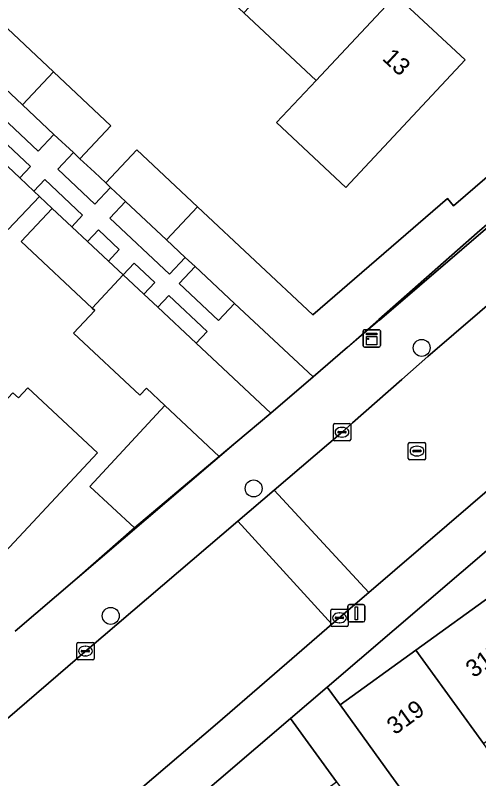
# Model space of a CAD drawing. Extents: x 159039 to 160102, y 381214 to 382524.
# Drawn here: x 159360.87 to 159387.61, y 381551.65 to 381595.72 of the extents above; entities that cross this region are included whole.
import ezdxf

# ---------------------------------------------------------------- set-up
doc = ezdxf.new("R2010")
doc.units = 0
for name, color, linetype in [('IMGEO_Boom', 7, 'Continuous'), ('IMGEO_Erf', 7, 'Continuous'), ('IMGEO_Groenvoorziening', 7, 'Continuous'), ('IMGEO_Kast', 7, 'Continuous'), ('IMGEO_Kolk', 7, 'Continuous'), ('IMGEO_Lichtmast', 7, 'Continuous'), ('IMGEO_Muur', 7, 'Continuous'), ('IMGEO_Pand', 7, 'Continuous'), ('IMGEO_Pand_nummerreeks', 7, 'Continuous'), ('IMGEO_Rijbaan_lokaal_gesloten', 7, 'Continuous'), ('IMGEO_Rijbaan_lokaal_open', 7, 'Continuous'), ('IMGEO_Rioolput', 7, 'Continuous'), ('IMGEO_Voetpad_open', 7, 'Continuous')]:
    doc.layers.add(name, color=color, linetype=linetype)

msp = doc.modelspace()

# ---------------------------------------------------------------- linework, layer by layer
at = {"layer": 'IMGEO_Boom'}
for centre in [(159384.322, 381576.519), (159374.624, 381568.41), (159366.375, 381561.05)]:
    msp.add_circle(centre, 0.489, dxfattribs=at)
at = {"layer": 'IMGEO_Erf'}
for points in [[(159358.121, 381620.029), (159362.065, 381616.336), (159366.187, 381612.475), (159370.397, 381608.534), (159374.52, 381604.672), (159378.667, 381600.788), (159382.839, 381596.881), (159386.831, 381593.143), (159379.941, 381585.785), (159375.948, 381589.524), (159378.229, 381591.959), (159374.057, 381595.866), (159369.91, 381599.75), (159365.786, 381603.611), (159361.577, 381607.553), (159357.455, 381611.414)], [(159359.739, 381595.573), (159363.073, 381592.45), (159366.39, 381589.344), (159364.602, 381587.436), (159365.432, 381586.658), (159366.093, 381586.039), (159367.881, 381587.947), (159371.392, 381584.659), (159378.048, 381578.425), (159385.803, 381585.139), (159386.165, 381584.722), (159388.093, 381586.391)], [(159360.868, 381560.164), (159364.448, 381563.227), (159367.747, 381566.141), (159365.174, 381568.516), (159369.495, 381573.198), (159368.434, 381574.191), (159368.052, 381573.783), (159364.224, 381577.368), (159365.451, 381578.677), (159365.305, 381578.814), (159361.204, 381582.655), (159362.999, 381584.572), (159362.261, 381585.263), (159360.466, 381583.346), (159357.233, 381586.374), (159353.085, 381590.258), (159354.881, 381592.176)], [(159389.45, 381584.825), (159387.521, 381583.155), (159381.857, 381578.152), (159381.88, 381578.125), (159388.939, 381584.182)], [(159403.941, 381578.38), (159378.876, 381556.936), (159379.618, 381555.911), (159383.989, 381559.075), (159388.621, 381562.428)], [(159360.734, 381573.932), (159361.052, 381573.634), (159361.598, 381574.217), (159365.612, 381570.457), (159358.919, 381563.31)], [(159383.781, 381540.929), (159381.468, 381544.123), (159383.599, 381545.666), (159382.675, 381546.943), (159380.544, 381545.4), (159377.268, 381549.925), (159379.399, 381551.468), (159376.754, 381555.121), (159362.339, 381542.788)]]:
    msp.add_lwpolyline(points, dxfattribs=at)
at = {"layer": 'IMGEO_Groenvoorziening'}
for points in [[(159358.954, 381592.724), (159358.057, 381591.767), (159362.196, 381587.88), (159363.098, 381588.843), (159361.285, 381590.541)], [(159357.412, 381591.058), (159356.787, 381590.39), (159359.028, 381588.291), (159361.125, 381586.327), (159361.752, 381586.998)], [(159365.432, 381586.658), (159364.602, 381587.436), (159364.22, 381587.793), (159363.316, 381586.828), (159365.459, 381584.816), (159366.366, 381585.783), (159366.093, 381586.039)], [(159362.566, 381586.235), (159361.939, 381585.565), (159362.261, 381585.263), (159362.999, 381584.572), (159364.128, 381583.515), (159364.756, 381584.186)], [(159367.233, 381584.971), (159366.325, 381584.002), (159369.768, 381580.769), (159370.68, 381581.743), (159369.604, 381582.751)], [(159365.663, 381583.337), (159365.035, 381582.666), (159366.245, 381581.534), (159366.873, 381582.205)], [(159367.73, 381581.404), (159367.101, 381580.732), (159368.293, 381579.616), (159368.922, 381580.288)], [(159371.246, 381581.214), (159370.333, 381580.239), (159372.604, 381578.106), (159373.52, 381579.084)], [(159369.724, 381579.537), (159369.095, 381578.864), (159371.31, 381576.79), (159371.941, 381577.463)]]:
    msp.add_lwpolyline(points, close=True, dxfattribs=at)
at = {"layer": 'IMGEO_Kast'}
for p, q in [((159380.938, 381576.646), (159380.938, 381577.487)), ((159380.938, 381577.487), (159380.938, 381576.646)), ((159381.013, 381577.571), (159381.854, 381577.571)), ((159381.854, 381577.571), (159381.013, 381577.571)), ((159381.938, 381577.496), (159381.938, 381576.655)), ((159381.938, 381576.655), (159381.938, 381577.496)), ((159381.863, 381576.571), (159381.022, 381576.571)), ((159381.022, 381576.571), (159381.863, 381576.571))]:
    msp.add_line(p, q, dxfattribs=at)
for points in [[(159381.133, 381577.361), (159381.733, 381577.361), (159381.733, 381577.276), (159381.133, 381577.276), (159381.133, 381577.361)], [(159381.133, 381577.186), (159381.733, 381577.186), (159381.733, 381576.697), (159381.133, 381576.697), (159381.133, 381577.186)]]:
    msp.add_lwpolyline(points, dxfattribs=at)
msp.add_circle((159381.217, 381577.035), 0.0377, dxfattribs=at)
for centre, start, end in [((159381.016, 381577.493), 92.4484, 184.2845), ((159381.016, 381577.493), 92.4484, 184.2845), ((159381.86, 381577.493), 2.4484, 94.2845), ((159381.86, 381577.493), 2.4484, 94.2845), ((159381.016, 381576.649), 182.4484, 274.2845), ((159381.016, 381576.649), 182.4484, 274.2845), ((159381.86, 381576.649), 272.4484, 4.2845), ((159381.86, 381576.649), 272.4484, 4.2845)]:
    msp.add_arc(centre, 0.0779, start, end, dxfattribs=at)
at = {"layer": 'IMGEO_Kolk'}
for p, q in [((159379.224, 381571.228), (159379.224, 381572.08)), ((159379.299, 381572.154), (159380.151, 381572.154)), ((159379.712, 381571.934), (159379.737, 381571.934)), ((159380.225, 381572.08), (159380.225, 381571.228)), ((159379.483, 381571.648), (159379.483, 381571.66)), ((159379.921, 381571.611), (159379.523, 381571.611)), ((159379.526, 381571.697), (159379.924, 381571.697)), ((159379.967, 381571.66), (159379.967, 381571.648)), ((159380.151, 381571.154), (159379.299, 381571.154)), ((159379.735, 381571.374), (159379.71, 381571.374)), ((159379.075, 381560.512), (159379.075, 381561.364)), ((159379.15, 381561.438), (159380.002, 381561.438)), ((159380.076, 381561.364), (159380.076, 381560.512)), ((159379.334, 381560.932), (159379.334, 381560.944)), ((159379.772, 381560.895), (159379.374, 381560.895)), ((159379.377, 381560.981), (159379.775, 381560.981)), ((159379.563, 381561.218), (159379.588, 381561.218)), ((159379.818, 381560.944), (159379.818, 381560.932)), ((159380.002, 381560.438), (159379.15, 381560.438)), ((159379.586, 381560.658), (159379.561, 381560.658)), ((159364.414, 381558.591), (159364.414, 381559.443)), ((159364.489, 381559.517), (159365.341, 381559.517)), ((159364.902, 381559.297), (159364.927, 381559.297)), ((159365.415, 381559.443), (159365.415, 381558.591)), ((159364.673, 381559.011), (159364.673, 381559.023)), ((159365.111, 381558.974), (159364.713, 381558.974)), ((159364.716, 381559.06), (159365.114, 381559.06)), ((159364.925, 381558.737), (159364.9, 381558.737)), ((159365.157, 381559.023), (159365.157, 381559.011)), ((159365.341, 381558.517), (159364.489, 381558.517))]:
    msp.add_line(p, q, dxfattribs=at)
for points in [[(159379.224, 381571.228), (159379.224, 381572.08)], [(159379.299, 381572.154), (159380.151, 381572.154)], [(159380.225, 381572.08), (159380.225, 381571.228)], [(159380.151, 381571.154), (159379.299, 381571.154)], [(159379.075, 381560.512), (159379.075, 381561.364)], [(159379.15, 381561.438), (159380.002, 381561.438)], [(159380.076, 381561.364), (159380.076, 381560.512)], [(159380.002, 381560.438), (159379.15, 381560.438)], [(159364.414, 381558.591), (159364.414, 381559.443)], [(159364.489, 381559.517), (159365.341, 381559.517)], [(159365.415, 381559.443), (159365.415, 381558.591)], [(159365.341, 381558.517), (159364.489, 381558.517)]]:
    msp.add_lwpolyline(points, dxfattribs=at)
for centre, radius, start, end in [((159379.301, 381572.078), 0.0765, 91.552, 178.448), ((159379.301, 381572.078), 0.0765, 91.552, 178.448), ((159380.149, 381572.078), 0.0765, 1.552, 88.448), ((159380.149, 381572.078), 0.0765, 1.552, 88.448), ((159379.523, 381571.657), 0.0403, 85.8775, 175.7526), ((159379.52, 381571.647), 0.0366, 178.938, 274.7102), ((159379.924, 381571.654), 0.043, 264.8664, 352.4533), ((159379.928, 381571.659), 0.0386, 1.7309, 96.639), ((159379.301, 381571.23), 0.0765, 181.552, 268.448), ((159379.301, 381571.23), 0.0765, 181.552, 268.448), ((159380.149, 381571.23), 0.0765, 271.552, 358.448), ((159380.149, 381571.23), 0.0765, 271.552, 358.448), ((159379.152, 381561.362), 0.0765, 91.552, 178.448), ((159379.152, 381561.362), 0.0765, 91.552, 178.448), ((159380, 381561.362), 0.0765, 1.552, 88.448), ((159380, 381561.362), 0.0765, 1.552, 88.448), ((159379.374, 381560.941), 0.0403, 85.8775, 175.7526), ((159379.371, 381560.931), 0.0366, 178.938, 274.7102), ((159379.775, 381560.938), 0.043, 264.8664, 352.4533), ((159379.779, 381560.943), 0.0386, 1.7309, 96.639), ((159379.152, 381560.514), 0.0765, 181.552, 268.448), ((159379.152, 381560.514), 0.0765, 181.552, 268.448), ((159380, 381560.514), 0.0765, 271.552, 358.448), ((159380, 381560.514), 0.0765, 271.552, 358.448), ((159364.491, 381559.441), 0.0765, 91.552, 178.448), ((159364.491, 381559.441), 0.0765, 91.552, 178.448), ((159365.339, 381559.441), 0.0765, 1.552, 88.448), ((159365.339, 381559.441), 0.0765, 1.552, 88.448), ((159364.713, 381559.02), 0.0403, 85.8775, 175.7526), ((159364.71, 381559.01), 0.0366, 178.938, 274.7102), ((159365.114, 381559.017), 0.043, 264.8664, 352.4533), ((159365.118, 381559.022), 0.0386, 1.7309, 96.639), ((159364.491, 381558.593), 0.0765, 181.552, 268.448), ((159364.491, 381558.593), 0.0765, 181.552, 268.448), ((159365.339, 381558.593), 0.0765, 271.552, 358.448), ((159365.339, 381558.593), 0.0765, 271.552, 358.448)]:
    msp.add_arc(centre, radius, start, end, dxfattribs=at)
for centre, major_axis, ratio, start_param, end_param in [((159379.711, 381571.654), (-0.387, 0.002), 0.722429, 4.712389, 7.853982), ((159379.736, 381571.654), (-0.39, 0.002), 0.717154, 1.570796, 4.712389), ((159379.562, 381560.938), (-0.387, 0.002), 0.722429, 4.712389, 7.853982), ((159379.587, 381560.938), (-0.39, 0.002), 0.717154, 1.570796, 4.712389), ((159364.901, 381559.017), (-0.387, 0.002), 0.722429, 4.712389, 7.853982), ((159364.926, 381559.017), (-0.39, 0.002), 0.717154, 1.570796, 4.712389)]:
    msp.add_ellipse(centre, major_axis=major_axis, ratio=ratio, start_param=start_param, end_param=end_param, dxfattribs=at)
at = {"layer": 'IMGEO_Lichtmast'}
for p, q in [((159380.055, 381560.802), (159380.055, 381561.602)), ((159380.055, 381561.602), (159380.055, 381560.802)), ((159380.155, 381561.702), (159380.945, 381561.702)), ((159380.945, 381561.702), (159380.155, 381561.702)), ((159381.045, 381561.602), (159381.045, 381560.802)), ((159381.045, 381560.802), (159381.045, 381561.602)), ((159380.945, 381560.702), (159380.155, 381560.702)), ((159380.155, 381560.702), (159380.945, 381560.702))]:
    msp.add_line(p, q, dxfattribs=at)
msp.add_lwpolyline([(159380.475, 381561.577), (159380.625, 381561.577), (159380.625, 381560.827), (159380.475, 381560.827), (159380.475, 381561.577)], dxfattribs=at)
for centre, start, end in [((159380.155, 381561.602), 90, 180), ((159380.155, 381561.602), 90, 180), ((159380.945, 381561.602), 0, 90), ((159380.945, 381561.602), 360, 90), ((159380.155, 381560.802), 180, 270), ((159380.155, 381560.802), 180, 270), ((159380.945, 381560.802), 270, 0), ((159380.945, 381560.802), 270, 0)]:
    msp.add_arc(centre, 0.1, start, end, dxfattribs=at)
at = {"layer": 'IMGEO_Muur'}
for points in [[(159380.047, 381576.553), (159388.939, 381584.182)], [(159364.448, 381563.227), (159373.593, 381571.052)]]:
    msp.add_lwpolyline(points, dxfattribs=at)
at = {"layer": 'IMGEO_Pand'}
for points in [[(159378.667, 381600.788), (159374.057, 381595.866), (159378.229, 381591.959), (159382.839, 381596.881)], [(159382.839, 381596.881), (159378.229, 381591.959), (159375.948, 381589.524), (159379.941, 381585.785), (159386.831, 381593.143)], [(159359.739, 381595.573), (159357.952, 381593.663), (159358.133, 381593.493), (159358.954, 381592.724), (159361.285, 381590.541), (159363.073, 381592.45)], [(159366.39, 381589.344), (159363.073, 381592.45), (159361.285, 381590.541), (159363.098, 381588.843), (159364.22, 381587.793), (159364.602, 381587.436)], [(159361.125, 381586.327), (159359.028, 381588.291), (159357.233, 381586.374), (159360.466, 381583.346), (159362.261, 381585.263), (159361.939, 381585.565)], [(159367.881, 381587.947), (159366.093, 381586.039), (159366.366, 381585.783), (159367.233, 381584.971), (159369.604, 381582.751), (159371.392, 381584.659)], [(159371.392, 381584.659), (159369.604, 381582.751), (159370.68, 381581.743), (159371.246, 381581.214), (159373.52, 381579.084), (159378.051, 381574.84), (159380.047, 381576.553), (159381.857, 381578.152), (159387.521, 381583.155), (159389.45, 381584.825), (159388.093, 381586.391), (159386.165, 381584.722), (159385.803, 381585.139), (159378.048, 381578.425)], [(159365.035, 381582.666), (159364.128, 381583.515), (159362.999, 381584.572), (159361.204, 381582.655), (159365.305, 381578.814), (159367.101, 381580.732), (159366.245, 381581.534)], [(159371.31, 381576.79), (159369.095, 381578.864), (159368.293, 381579.616), (159367.101, 381580.732), (159365.305, 381578.814), (159365.451, 381578.677), (159364.224, 381577.368), (159368.052, 381573.783), (159368.434, 381574.191), (159369.495, 381573.198), (159372.64, 381570.252), (159373.593, 381571.052), (159375.619, 381572.754)], [(159354.587, 381567.367), (159358.919, 381563.31), (159365.612, 381570.457), (159361.598, 381574.217), (159361.052, 381573.634), (159360.734, 381573.932)], [(159372.64, 381570.252), (159369.495, 381573.198), (159365.174, 381568.516), (159367.747, 381566.141)], [(159392.521, 381557.042), (159388.621, 381562.428), (159383.989, 381559.075), (159387.888, 381553.689), (159388.256, 381553.955)], [(159387.888, 381553.689), (159383.989, 381559.075), (159379.618, 381555.911), (159382.55, 381551.861), (159385.277, 381548.095), (159389.647, 381551.259)]]:
    msp.add_lwpolyline(points, close=True, dxfattribs=at)
at = {"layer": 'IMGEO_Rijbaan_lokaal_gesloten'}
msp.add_lwpolyline([(159396.399, 381585.982), (159389.177, 381579.892), (159384.685, 381576.02), (159383.18, 381574.694), (159380.332, 381572.186), (159379.759, 381571.681), (159375.809, 381568.311), (159381.263, 381562.391), (159391.641, 381571.315), (159401.441, 381579.651), (159403.253, 381581.19)], dxfattribs=at)
msp.add_lwpolyline([(159351.483, 381536.862), (159356.146, 381540.888), (159356.286, 381541.009), (159361.516, 381545.448), (159372.533, 381554.867), (159375.25, 381557.212), (159377.401, 381559.069), (159379.14, 381560.565), (159373.717, 381566.526), (159365.008, 381559.095), (159359.838, 381554.65), (159355.305, 381550.753), (159343.919, 381541.049), (159342.601, 381539.925), (159329.876, 381529.002), (159334.842, 381522.599), (159346.704, 381532.736), (159349.151, 381534.849)], close=True, dxfattribs=at)
at = {"layer": 'IMGEO_Rijbaan_lokaal_open'}
msp.add_lwpolyline([(159381.263, 381562.391), (159375.809, 381568.311), (159373.717, 381566.526), (159379.14, 381560.565)], close=True, dxfattribs=at)
at = {"layer": 'IMGEO_Rioolput'}
for p, q in [((159383.625, 381571.065), (159384.477, 381571.065)), ((159383.55, 381570.139), (159383.55, 381570.991)), ((159383.809, 381570.559), (159383.809, 381570.571)), ((159383.852, 381570.608), (159384.25, 381570.608)), ((159384.038, 381570.845), (159384.063, 381570.845)), ((159384.293, 381570.571), (159384.293, 381570.559)), ((159384.551, 381570.991), (159384.551, 381570.139)), ((159384.247, 381570.522), (159383.849, 381570.522)), ((159384.061, 381570.285), (159384.036, 381570.285)), ((159384.477, 381570.065), (159383.625, 381570.065))]:
    msp.add_line(p, q, dxfattribs=at)
for points in [[(159383.625, 381571.065), (159384.477, 381571.065)], [(159383.55, 381570.139), (159383.55, 381570.991)], [(159384.551, 381570.991), (159384.551, 381570.139)], [(159384.477, 381570.065), (159383.625, 381570.065)]]:
    msp.add_lwpolyline(points, dxfattribs=at)
for centre, radius, start, end in [((159383.627, 381570.989), 0.0765, 91.552, 178.448), ((159383.627, 381570.989), 0.0765, 91.552, 178.448), ((159384.475, 381570.989), 0.0765, 1.552, 88.448), ((159384.475, 381570.989), 0.0765, 1.552, 88.448), ((159383.849, 381570.568), 0.0403, 85.8775, 175.7526), ((159383.846, 381570.558), 0.0366, 178.938, 274.7102), ((159384.25, 381570.565), 0.043, 264.8664, 352.4533), ((159384.254, 381570.57), 0.0386, 1.7309, 96.639), ((159383.627, 381570.141), 0.0765, 181.552, 268.448), ((159383.627, 381570.141), 0.0765, 181.552, 268.448), ((159384.475, 381570.141), 0.0765, 271.552, 358.448), ((159384.475, 381570.141), 0.0765, 271.552, 358.448)]:
    msp.add_arc(centre, radius, start, end, dxfattribs=at)
for centre, major_axis, ratio, start_param, end_param in [((159384.037, 381570.565), (-0.387, 0.002), 0.722429, 4.712389, 7.853982), ((159384.062, 381570.565), (-0.39, 0.002), 0.717154, 1.570796, 4.712389)]:
    msp.add_ellipse(centre, major_axis=major_axis, ratio=ratio, start_param=start_param, end_param=end_param, dxfattribs=at)
at = {"layer": 'IMGEO_Voetpad_open'}
for points in [[(159357.412, 381591.058), (159361.752, 381586.998), (159361.125, 381586.327), (159361.939, 381585.565), (159362.566, 381586.235), (159364.756, 381584.186), (159364.128, 381583.515), (159365.035, 381582.666), (159365.663, 381583.337), (159366.873, 381582.205), (159366.245, 381581.534), (159367.101, 381580.732), (159367.73, 381581.404), (159368.922, 381580.288), (159368.293, 381579.616), (159369.095, 381578.864), (159369.724, 381579.537), (159371.941, 381577.463), (159371.31, 381576.79), (159375.619, 381572.754), (159378.051, 381574.84), (159373.52, 381579.084), (159372.604, 381578.106), (159370.333, 381580.239), (159371.246, 381581.214), (159370.68, 381581.743), (159369.768, 381580.769), (159366.325, 381584.002), (159367.233, 381584.971), (159366.366, 381585.783), (159365.459, 381584.816), (159363.316, 381586.828), (159364.22, 381587.793), (159363.098, 381588.843), (159362.196, 381587.88), (159358.057, 381591.767)], [(159393.769, 381588.327), (159388.939, 381584.182), (159381.88, 381578.125), (159381.857, 381578.152), (159380.047, 381576.553), (159378.051, 381574.84), (159375.619, 381572.754), (159373.593, 381571.052), (159372.64, 381570.252), (159367.747, 381566.141), (159364.448, 381563.227), (159360.868, 381560.164)], [(159319.433, 381520.175), (159327.779, 381527.216), (159328.715, 381528.006), (159329.876, 381529.002), (159342.601, 381539.925), (159343.919, 381541.049), (159355.305, 381550.753), (159359.838, 381554.65), (159365.008, 381559.095), (159373.717, 381566.526), (159375.809, 381568.311), (159379.759, 381571.681), (159380.332, 381572.186), (159383.18, 381574.694), (159384.685, 381576.02), (159389.177, 381579.892), (159396.399, 381585.982)], [(159362.339, 381542.788), (159376.754, 381555.121), (159378.876, 381556.936), (159403.941, 381578.38), (159409.603, 381583.191)], [(159403.253, 381581.19), (159401.441, 381579.651), (159391.641, 381571.315), (159381.263, 381562.391), (159379.14, 381560.565), (159377.401, 381559.069), (159375.25, 381557.212), (159372.533, 381554.867), (159361.516, 381545.448), (159356.286, 381541.009), (159356.146, 381540.888), (159351.483, 381536.862), (159349.151, 381534.849), (159346.704, 381532.736), (159334.842, 381522.599), (159332.693, 381520.763), (159317.66, 381507.94), (159308.43, 381500), (159302.188, 381494.631), (159301.064, 381493.711)]]:
    msp.add_lwpolyline(points, dxfattribs=at)
msp.add_lwpolyline([(159382.55, 381551.861), (159379.618, 381555.911), (159378.876, 381556.936), (159376.754, 381555.121), (159379.399, 381551.468), (159382.675, 381546.943), (159383.599, 381545.666), (159385.911, 381542.472), (159388.144, 381539.388), (159390.327, 381540.843), (159388.772, 381542.991), (159385.277, 381548.095)], close=True, dxfattribs=at)

# ---------------------------------------------------------------- texts
at = {"layer": 'IMGEO_Pand_nummerreeks'}
for s, rotation, p in [('13', 316.8786, (159381.999, 381593.174)), ('317', 35.8958, (159387.324, 381557.44)), ('319', 35.8958, (159382.774, 381554.147))]:
    msp.add_text(s, height=1, rotation=rotation, dxfattribs=at).set_placement(p)

doc.saveas('drawing.dxf')
